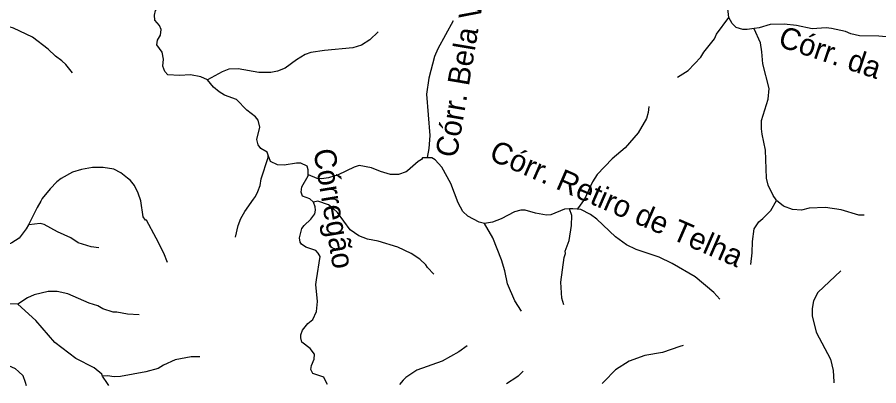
# Model space of a CAD drawing. Extents: x 393 to 446.6, y 8175.5 to 8231.
# Drawn here: x 415.52 to 421.85, y 8175.57 to 8178.28 of the extents above; entities that cross this region are included whole.
import ezdxf
from ezdxf.enums import TextEntityAlignment as Align

# ---------------------------------------------------------------- set-up
doc = ezdxf.new("R2010")
doc.units = 0
doc.header["$LTSCALE"] = 0.064
doc.linetypes.add('LONG_DASHED', pattern=[7.5, 6, -1.5])
doc.layers.add('61', color=7, linetype='Continuous')
doc.layers.add('7', color=7, linetype='Continuous', lineweight=25)
doc.layers.add('9', color=7, linetype='LONG_DASHED', lineweight=25)

msp = doc.modelspace()

# ---------------------------------------------------------------- linework, layer by layer
at = {"layer": '7'}
for points in [[(420.7473, 8178.2768), (420.7304, 8178.4294), (420.7143, 8178.4939), (420.7143, 8178.5198), (420.7272, 8178.5715), (420.7272, 8178.6231), (420.7178, 8178.6435)], [(416.9156, 8177.8185), (416.8646, 8177.8415), (416.7903, 8177.8561), (416.7096, 8177.8512), (416.624, 8177.8544), (416.5998, 8177.8803), (416.5852, 8177.9191), (416.5901, 8177.9708), (416.582, 8178.0224), (416.5416, 8178.0773), (416.5465, 8178.1096), (416.5691, 8178.1484), (416.5739, 8178.1887), (416.5626, 8178.2194), (416.5271, 8178.2582), (416.5239, 8178.2937), (416.5335, 8178.3276), (416.5529, 8178.3518), (416.5723, 8178.3906), (416.5836, 8178.439), (416.5852, 8178.481), (416.5697, 8178.5612)], [(420.3699, 8177.8387), (420.4478, 8177.8884), (420.5415, 8177.9853), (420.5641, 8178.0224), (420.6416, 8178.1193), (420.6577, 8178.1548), (420.7473, 8178.2768)], [(420.9325, 8178.1951), (420.8822, 8178.1887), (420.8499, 8178.1887), (420.8015, 8178.2033), (420.7708, 8178.2323), (420.7473, 8178.2768)], [(415.9215, 8177.8696), (415.8726, 8177.9325), (415.844, 8177.9594), (415.7972, 8177.9934), (415.7439, 8178.045), (415.6277, 8178.1322), (415.4888, 8178.1984), (415.4565, 8178.2081), (415.4291, 8178.2049), (415.3834, 8178.211)], [(421.9832, 8178.1276), (421.8511, 8178.1387), (421.709, 8178.1419), (421.6444, 8178.158), (421.6057, 8178.1742), (421.5023, 8178.1968), (421.4636, 8178.2), (421.3602, 8178.1936), (421.2439, 8178.2178), (421.1535, 8178.2291), (421.0502, 8178.2259), (420.971, 8178.2), (420.9325, 8178.1951)], [(418.1695, 8178.1709), (418.108, 8178.1128), (418.0466, 8178.0741), (417.9821, 8178.0531), (417.7754, 8178.0353), (417.6752, 8178.0192), (417.6316, 8178.0046), (417.5687, 8177.9659), (417.4863, 8177.9045), (417.4298, 8177.8819), (417.3814, 8177.8738), (417.2909, 8177.8738), (417.1391, 8177.8997), (417.0713, 8177.898), (417.0229, 8177.8787), (416.9156, 8177.8185)], [(421.0988, 8176.9322), (421.0947, 8176.9357), (421.0744, 8176.9679), (421.0372, 8177.0439), (421.0243, 8177.0955), (421.0178, 8177.3022), (420.992, 8177.4185), (420.9888, 8177.4572), (420.9888, 8177.5186), (421.0372, 8177.6769), (421.0437, 8177.7544), (420.9969, 8177.9352), (420.9904, 8178.0257), (420.9791, 8178.0902), (420.9336, 8178.1927), (420.9325, 8178.1951)], [(417.3608, 8177.265), (417.3525, 8177.2874), (417.306, 8177.313), (417.2862, 8177.3409), (417.278, 8177.3797), (417.299, 8177.4702), (417.286, 8177.5218), (417.2667, 8177.5477), (417.2037, 8177.5961), (417.1278, 8177.6736), (417.039, 8177.7059), (417.0002, 8177.7301), (416.9598, 8177.7657), (416.9156, 8177.8185)], [(420.1591, 8177.6224), (420.1556, 8177.5781), (420.1427, 8177.5345), (420.0797, 8177.4282), (419.9844, 8177.3184), (419.8907, 8177.2376), (419.7793, 8177.123), (419.7454, 8177.0697), (419.6872, 8176.9405), (419.6354, 8176.87), (419.6335, 8176.8674)], [(417.1215, 8176.6624), (417.1391, 8176.7467), (417.1601, 8176.7984), (417.1892, 8176.8501), (417.2537, 8176.9412), (417.267, 8176.96), (417.2844, 8176.9986), (417.3006, 8177.0406), (417.3086, 8177.0906), (417.3603, 8177.2473), (417.3607, 8177.2618), (417.3608, 8177.265)], [(417.6557, 8177.1198), (417.6557, 8177.1577), (417.6478, 8177.1827), (417.601, 8177.2069), (417.5687, 8177.2069), (417.4782, 8177.1908), (417.4298, 8177.1924), (417.3781, 8177.2183), (417.3608, 8177.265)], [(418.5289, 8177.2448), (418.4947, 8177.244), (418.4891, 8177.2327), (418.4633, 8177.2182), (418.3848, 8177.1499), (418.3761, 8177.1423), (418.3179, 8177.1213), (418.2598, 8177.1213), (418.1855, 8177.1439), (418.1209, 8177.1714), (418.0305, 8177.1875), (417.9917, 8177.1762), (417.8755, 8177.1197), (417.8034, 8177.0982), (417.7528, 8177.0906), (417.7205, 8177.0939), (417.6562, 8177.1196), (417.6557, 8177.1198)], [(418.951, 8176.7613), (418.9121, 8176.7709), (418.8282, 8176.8161), (418.7927, 8176.8501), (418.7571, 8176.9147), (418.7038, 8177.0568), (418.6376, 8177.1763), (418.5892, 8177.2311), (418.5634, 8177.2457), (418.5289, 8177.2448)], [(416.6202, 8176.4748), (416.5934, 8176.5435), (416.5368, 8176.6531), (416.4657, 8176.7855), (416.4577, 8176.7871), (416.4415, 8176.8113), (416.4237, 8176.9276), (416.4044, 8176.9857), (416.3769, 8177.0406), (416.3478, 8177.0794), (416.3259, 8177.0967), (416.2784, 8177.1343), (416.2252, 8177.1617), (416.1477, 8177.1746), (416.0701, 8177.173), (415.9878, 8177.1601), (415.9216, 8177.1391), (415.8376, 8177.0939), (415.8069, 8177.068), (415.7568, 8177.018), (415.7003, 8176.9453), (415.6892, 8176.9267), (415.6616, 8176.8808), (415.5978, 8176.7532)], [(417.6942, 8176.92), (417.6672, 8176.9437), (417.6123, 8176.9631), (417.6042, 8176.9922), (417.609, 8177.0325), (417.6557, 8177.1134), (417.6557, 8177.1198)], [(417.7967, 8175.5772), (417.7882, 8175.5946), (417.7705, 8175.6309), (417.6898, 8175.6599), (417.6752, 8175.6874), (417.6784, 8175.7165), (417.6978, 8175.7649), (417.7011, 8175.8021), (417.6704, 8175.8425), (417.6074, 8175.8892), (417.6009, 8175.92), (417.6009, 8175.9426), (417.6139, 8175.9781), (417.6526, 8176.0265), (417.6881, 8176.0572), (417.7172, 8176.1137), (417.7237, 8176.188), (417.7107, 8176.3123), (417.7161, 8176.3466), (417.7431, 8176.519), (417.7291, 8176.5445), (417.7107, 8176.5626), (417.6365, 8176.5885), (417.6058, 8176.6094), (417.5961, 8176.624), (417.5912, 8176.6563), (417.609, 8176.7241), (417.6251, 8176.7483), (417.6752, 8176.7951), (417.7043, 8176.8323), (417.7075, 8176.8598), (417.7059, 8176.8856), (417.6942, 8176.92)], [(418.5794, 8176.3897), (418.5327, 8176.4383), (418.5197, 8176.4593), (418.4762, 8176.4997), (418.4116, 8176.5416), (418.3147, 8176.5869), (418.1694, 8176.6321), (418.0919, 8176.6466), (418.0273, 8176.6724), (417.9643, 8176.716), (417.8697, 8176.8435), (417.8382, 8176.8726), (417.8033, 8176.8982), (417.7265, 8176.9255), (417.6942, 8176.92)], [(420.9082, 8176.4612), (420.9194, 8176.5465), (420.921, 8176.6305), (420.9339, 8176.7225), (420.9676, 8176.7754), (420.9985, 8176.7984), (421.0566, 8176.8581), (421.0986, 8176.9319), (421.0988, 8176.9322)], [(421.7434, 8176.8245), (421.7026, 8176.8245), (421.5734, 8176.8614), (421.4571, 8176.8791), (421.3376, 8176.8743), (421.2827, 8176.8597), (421.2149, 8176.8646), (421.1503, 8176.8888), (421.0988, 8176.9322)], [(419.5756, 8176.8696), (419.5394, 8176.8675), (419.4386, 8176.8258), (419.4063, 8176.8242), (419.3256, 8176.8371), (419.2513, 8176.8613), (419.219, 8176.8613), (419.1705, 8176.8484), (419.0737, 8176.7968), (419.0091, 8176.7709), (418.951, 8176.7613)], [(419.5348, 8176.1642), (419.5197, 8176.213), (419.5129, 8176.3301), (419.5371, 8176.511), (419.5468, 8176.5416), (419.5443, 8176.5578), (419.5742, 8176.6369), (419.5904, 8176.7467), (419.592, 8176.821), (419.5756, 8176.8696)], [(419.6335, 8176.8674), (419.6011, 8176.871), (419.5756, 8176.8696)], [(420.6823, 8176.2055), (420.6384, 8176.2542), (420.4995, 8176.3688), (420.33, 8176.469), (420.2347, 8176.5142), (420.0651, 8176.5707), (419.9941, 8176.6062), (419.915, 8176.6644), (419.7777, 8176.7936), (419.7293, 8176.8274), (419.6582, 8176.8646), (419.6335, 8176.8674)], [(415.5978, 8176.7532), (415.5824, 8176.7225), (415.5292, 8176.6547), (415.4759, 8176.6208), (415.3596, 8176.5675), (415.337, 8176.5513), (415.3063, 8176.5239), (415.1804, 8176.3672), (415.14, 8176.3446), (415.1027, 8176.3346), (415.0992, 8176.3337)], [(416.1159, 8176.5839), (416.06, 8176.5909), (415.9636, 8176.6208), (415.9103, 8176.6563), (415.8118, 8176.6999), (415.7149, 8176.7548), (415.6842, 8176.7629), (415.6003, 8176.7535), (415.5978, 8176.7532)], [(419.224, 8176.1165), (419.1737, 8176.1945), (419.1205, 8176.3172), (419.1011, 8176.4141), (419.0769, 8176.4948), (419.0123, 8176.6563), (418.951, 8176.7613)], [(416.4114, 8176.0911), (416.3253, 8176.0943), (416.2478, 8176.1105), (416.2219, 8176.1105), (416.1444, 8176.1347), (416.1089, 8176.1557), (416.0443, 8176.1751), (415.8877, 8176.2445), (415.8085, 8176.2623), (415.744, 8176.2623), (415.6406, 8176.2364), (415.5922, 8176.2154), (415.5196, 8176.1677)], [(415.5196, 8176.1677), (415.4081, 8176.1702), (415.3435, 8176.1638), (415.2143, 8176.1783)], [(415.5832, 8175.5686), (415.5754, 8175.5925), (415.5598, 8175.6406), (415.5243, 8175.6745), (415.5033, 8175.6923), (415.4097, 8175.7358), (415.3612, 8175.7811), (415.3402, 8175.8198), (415.316, 8175.907), (415.2207, 8176.1428), (415.2143, 8176.1783)], [(416.1433, 8175.6402), (416.1371, 8175.6528), (416.0814, 8175.7003), (415.9458, 8175.7697), (415.7924, 8175.886), (415.6535, 8176.0491), (415.5196, 8176.1677)], [(420.4116, 8175.8654), (420.3867, 8175.8569), (420.2589, 8175.8134), (420.1297, 8175.7924), (420.0135, 8175.7504), (419.9134, 8175.6858), (419.8294, 8175.5986), (419.8161, 8175.5848)], [(418.8229, 8175.862), (418.7636, 8175.8182), (418.6409, 8175.7504), (418.4536, 8175.6825), (418.3728, 8175.6293), (418.3531, 8175.6102), (418.3266, 8175.5792)], [(416.859, 8175.7811), (416.7936, 8175.781), (416.6778, 8175.7584), (416.5901, 8175.721), (416.5518, 8175.6957), (416.4614, 8175.6714), (416.2753, 8175.6366), (416.2277, 8175.6341), (416.1803, 8175.6406), (416.1433, 8175.6402)], [(419.2352, 8175.6758), (419.1988, 8175.6397), (419.1899, 8175.6309), (419.1139, 8175.5822)], [(416.188, 8175.571), (416.1791, 8175.5853), (416.1433, 8175.6402)]]:
    msp.add_lwpolyline(points, dxfattribs=at)
at = {"layer": '9'}
for points in [[(418.7203, 8178.253), (418.6072, 8178.0455), (418.5841, 8177.9908), (418.5407, 8177.8319), (418.5247, 8177.7143), (418.5504, 8177.4094), (418.5424, 8177.3132), (418.5296, 8177.2486), (418.5289, 8177.2448)], [(421.5705, 8176.4144), (421.4006, 8176.2542), (421.3699, 8176.1944), (421.3602, 8176.1363), (421.3602, 8176.083), (421.3892, 8175.9619), (421.4942, 8175.7633), (421.5152, 8175.681), (421.5185, 8175.5986), (421.5188, 8175.591)]]:
    msp.add_lwpolyline(points, dxfattribs=at)

# ---------------------------------------------------------------- texts
at = {"layer": '61'}
for s, rotation, p in [('Córr. Bela Vista', 80.422, (418.8713, 8177.9794)), ('Córr. da Capoeira', 341.533, (421.9077, 8177.7986)), ('Córr. Retiro de Telha', 336.473, (419.8919, 8176.836)), ('Córregão', 279.442, (417.7656, 8176.8599))]:
    msp.add_text(s, height=0.16, rotation=rotation, dxfattribs=at).set_placement(p, align=Align.CENTER)

doc.saveas('drawing.dxf')
